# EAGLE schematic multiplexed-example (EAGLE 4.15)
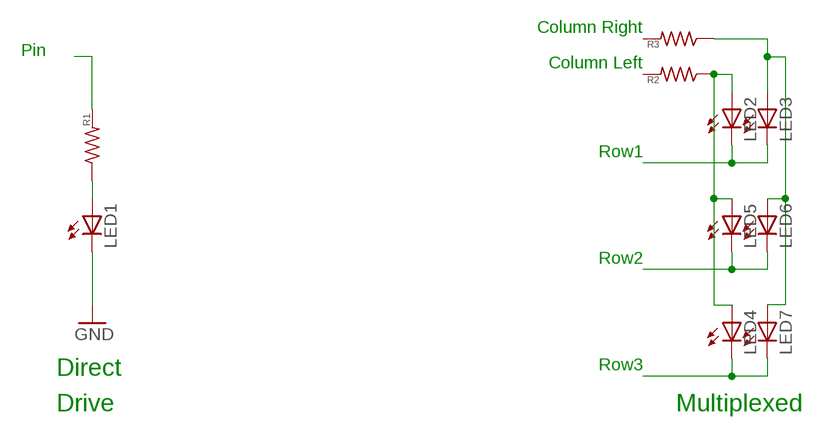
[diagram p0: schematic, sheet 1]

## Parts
LED1  LED5MM  [LED5MM]
LED2  LED5MM  [LED5MM]
LED3  LED5MM  [LED5MM]
LED4  LED5MM  [LED5MM]
LED5  LED5MM  [LED5MM]
LED6  LED5MM  [LED5MM]
LED7  LED5MM  [LED5MM]
R1  R-US_0207/10  [0207/10]
R2  R-US_0207/10  [0207/10]
R3  R-US_0207/10  [0207/10]

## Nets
GND: LED1.K(C)
N$1: LED2.A LED4.A LED5.A R2.1
N$2: LED3.A LED6.A LED7.A R3.1
N$3: LED2.K(C) LED3.K(C)
N$4: LED5.K(C) LED6.K(C)
N$5: LED4.K(C) LED7.K(C)
N$11: LED1.A R1.1
N$13: R1.2
Unconnected: R2.2 R3.2

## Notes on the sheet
- Column Right
- Pin | Column Left
- Row1
- Row2
- Row3
- Direct
- Multiplexed
- Drive

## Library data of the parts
LED1-LED7 = led:LED: LED
R1-R3 = my-rcl:R-US_: RESISTOR, American symbol

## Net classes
0 default: width 0.6 mm
1 power: width 1 mm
